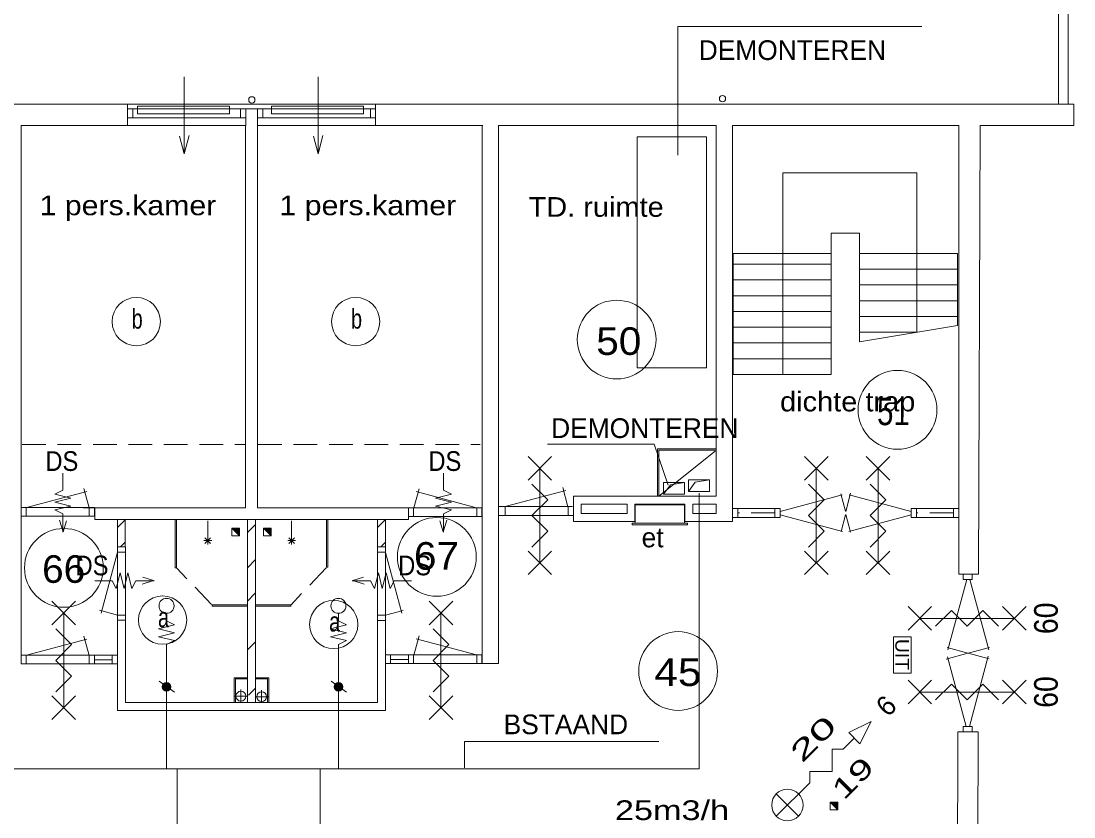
# Model space of a CAD drawing. Extents: x 295824 to 414724, y 24924 to 109024.
# Drawn here: x 320090 to 333452, y 38482 to 48585 of the extents above; entities that cross this region are included whole.
import ezdxf
from ezdxf.enums import TextEntityAlignment as Align

# ---------------------------------------------------------------- set-up
doc = ezdxf.new("R2010")
doc.units = 0
doc.header["$LTSCALE"] = 100
doc.linetypes.add('DOT_DASHED', pattern=[7.7, 5, -1.2, 0.3, -1.2])
doc.linetypes.add('MEDIUM_DASHED', pattern=[4.5, 3, -1.5])
for name, color, linetype, lineweight in [('1', 7, 'Continuous', 13), ('16', 7, 'Continuous', 13), ('24', 7, 'Continuous', 13), ('61', 7, 'Continuous', 13)]:
    doc.layers.add(name, color=color, linetype=linetype, lineweight=lineweight)

msp = doc.modelspace()

# ---------------------------------------------------------------- hatches: boundary and pattern name
at = {"layer": '24'}
for points in [[(321990.4, 40135, 1), (321881.8, 40135, 1)], [(324172.4, 40135, 1), (324063.7, 40135, 1)]]:
    msp.add_hatch(color=256, dxfattribs=at).paths.add_polyline_path(points)
at = {"layer": '61'}
for points in [[(322863, 42048.6), (322763, 42148.6), (322863, 42148.6)], [(323266, 42048.6), (323166, 42148.6), (323266, 42148.6)], [(330456.2, 38570.7), (330356.2, 38670.7), (330456.2, 38670.7)]]:
    msp.add_hatch(color=256, dxfattribs=at).paths.add_polyline_path(points)

# ---------------------------------------------------------------- linework, layer by layer
at = {"layer": '1'}
for p, q in [((321936.1, 40103.6), (321936.1, 39093.2)), ((324118, 40097), (324118, 39093.2)), ((322069.3, 38210.2), (322069.3, 39093.2)), ((323884.9, 38205.2), (323884.9, 39093.2))]:
    msp.add_line(p, q, dxfattribs=at)
msp.add_lwpolyline([(328302.1, 42694.8), (328124.9, 43212.8), (326770.6, 43212.8)], dxfattribs=at)
at = {"layer": '16'}
for p, q in [((320520.3, 42478.5), (320720.3, 42528.5)), ((325550.6, 42478.5), (325350.6, 42528.5)), ((321396.7, 41380.3), (321346.7, 41580.3)), ((324674.2, 41380.3), (324724.2, 41580.3))]:
    msp.add_line(p, q, dxfattribs=at)
at = {"layer": '24'}
for p, q in [((322161, 46901.4), (322101.4, 47123.8)), ((323859.9, 46901.4), (323800.3, 47123.8)), ((328693.9, 42590.3), (328693.9, 39093.2)), ((320623.7, 42103.1), (320578.6, 42247.3)), ((320666.1, 42238.9), (320623.7, 42103.1)), ((325404.8, 42238.9), (325447.2, 42103.1)), ((325447.2, 42103.1), (325492.2, 42247.3)), ((321772.1, 41483.7), (321627.9, 41438.7)), ((321636.3, 41526.2), (321772.1, 41483.7)), ((324434.5, 41526.2), (324298.7, 41483.7)), ((324298.7, 41483.7), (324442.9, 41438.7)), ((321936.1, 40620.3), (321936.1, 40080.9)), ((324118, 40620.3), (324118, 40112)), ((321844.5, 40205.8), (322036, 40064.1)), ((324026.4, 40205.8), (324218, 40064.1)), ((304097.2, 39093.2), (328693.9, 39093.2))]:
    msp.add_line(p, q, dxfattribs=at)
for points in [[(328423.7, 46882.6), (328423.7, 48515.9), (331521.8, 48515.9)], [(322161, 47876.3), (322161, 46901.4), (322222.6, 47131.6)], [(323859.9, 47876.3), (323859.9, 46901.4), (323921.6, 47131.6)], [(320720.3, 42528.5), (320520.3, 42578.5), (320620.3, 42628.5), (320620.3, 42847.3)], [(325350.6, 42528.5), (325550.6, 42578.5), (325450.6, 42628.5), (325450.6, 42847.3)], [(328560.2, 42611.9), (328646.7, 42731.9), (328827.5, 42761.4)], [(328243.8, 42578.6), (328330.3, 42698.6), (328511.1, 42728.1)], [(320620.3, 42097.3), (320620.3, 42328.5), (320520.3, 42378.5), (320720.3, 42428.5), (320520.3, 42478.5)], [(325450.6, 42097.3), (325450.6, 42328.5), (325550.6, 42378.5), (325350.6, 42428.5), (325550.6, 42478.5)], [(321346.7, 41580.3), (321296.7, 41380.3), (321246.7, 41480.3), (321027.9, 41480.3)], [(321777.9, 41480.3), (321546.7, 41480.3), (321496.7, 41380.3), (321446.7, 41580.3), (321396.7, 41380.3)], [(324292.9, 41480.3), (324524.2, 41480.3), (324574.2, 41380.3), (324624.2, 41580.3), (324674.2, 41380.3)], [(324724.2, 41580.3), (324774.2, 41380.3), (324824.2, 41480.3), (325042.9, 41480.3)], [(321936.1, 41070.3), (321936.1, 40970.3), (322036.1, 40920.3), (321836.1, 40870.3), (322036.1, 40820.3), (321836.1, 40770.3), (322036.1, 40720.3), (321936.1, 40670.3), (321936.1, 40620.3)], [(324118, 41070.3), (324118, 40970.3), (324218, 40920.3), (324018, 40870.3), (324218, 40820.3), (324018, 40770.3), (324218, 40720.3), (324118, 40670.3), (324118, 40620.3)], [(325717.8, 39105.3), (325717.8, 39438.6), (328182.9, 39438.6)]]:
    msp.add_lwpolyline(points, dxfattribs=at)
for points in [[(321569.6, 47405.5), (322735.6, 47405.5), (322735.6, 47505.5), (321569.6, 47505.5)], [(323268.6, 47405.5), (324434.5, 47405.5), (324434.5, 47505.5), (323268.6, 47505.5)], [(327907.4, 44182.7), (328790.1, 44182.7), (328790.1, 47115.9), (327907.4, 47115.9)], [(328560.2, 42611.9), (328827.5, 42611.9), (328827.5, 42761.4), (328560.2, 42761.4)], [(328243.8, 42578.6), (328511.1, 42578.6), (328511.1, 42728.1), (328243.8, 42728.1)]]:
    msp.add_lwpolyline(points, close=True, dxfattribs=at)
for centre, radius in [((321936.1, 41162), 95), ((324118, 41162), 95), ((321936.1, 40135), 54.3), ((324118.1, 40135), 54.3)]:
    msp.add_circle(centre, radius, dxfattribs=at)
at = {"layer": '61'}
for p, q in [((333257, 47527.9), (333257, 54115.7)), ((333377, 54115.7), (333377, 47527.2)), ((301828.9, 47527.9), (333452, 47527.9)), ((313820.3, 47527.9), (333174.1, 47527.9)), ((321441.1, 47257.3), (321441.1, 47527.3)), ((321442, 47472.1), (322941, 47472.1)), ((321442, 47358.1), (321442, 47472.1)), ((321509, 47358.1), (321509, 47471.5)), ((322874, 47472.1), (324590, 47472.1)), ((322874, 47358.5), (322874, 47472.1)), ((322941, 47359.1), (322941, 47472.1)), ((322941.1, 47257.3), (322941.1, 47472.1)), ((323090.1, 47257.3), (323090.1, 47472.1)), ((323090.9, 47358.1), (323090.9, 47472.1)), ((323157.9, 47358.1), (323157.9, 47471.5)), ((324523, 47358.5), (324523, 47471.5)), ((324590, 47359.1), (324590, 47472.1)), ((324590.1, 47257.3), (324590.1, 47527.3)), ((333452, 47527.9), (333452, 47257.9)), ((321442, 47358.1), (322940, 47358.1)), ((323090.9, 47358.1), (324589, 47358.1)), ((320090.1, 47257.9), (322941.2, 47257.9)), ((320090.1, 40532.9), (320090.1, 47257.9)), ((320090.4, 47257.9), (322940.4, 47257.9)), ((320090.5, 47257.9), (322940.5, 47257.9)), ((322940.1, 47257.9), (322940.1, 42407.9)), ((325940.1, 47257.9), (323090.1, 47257.9)), ((325949, 47257.9), (323099, 47257.9)), ((325940.1, 40428.5), (325940.1, 47257.9)), ((328910.1, 47257.9), (328910.1, 42552.9)), ((332260.1, 47257.9), (332241.7, 41563.5)), ((333452, 47257.9), (332260.1, 47257.9)), ((330368.9, 45635), (330368.9, 45892.9)), ((330368.9, 45892.9), (330732.6, 45892.9)), ((330732.6, 45635), (330732.6, 45892.9)), ((331972.5, 45635), (330732.6, 45635)), ((331972.5, 44722.2), (331972.5, 45635)), ((329129, 45498.6), (330368.9, 45498.6)), ((331972.5, 45435), (330732.6, 45435)), ((329129, 45298.6), (330368.9, 45298.6)), ((331972.5, 45235), (330732.6, 45235)), ((329129, 45098.6), (330368.9, 45098.6)), ((331972.5, 45035), (330732.6, 45035)), ((329129, 44898.6), (330368.9, 44898.6)), ((331972.5, 44835), (330732.6, 44835)), ((329129, 44698.6), (330368.9, 44698.6)), ((330732.6, 44511), (331972.5, 44722.2)), ((331460.5, 44635), (330732.6, 44635)), ((329129, 44498.6), (330368.9, 44498.6)), ((329129, 44298.6), (330368.9, 44298.6)), ((329129, 44098.6), (330368.9, 44098.6)), ((326523.6, 42757.7), (326823.6, 43057.7)), ((326823.6, 42757.7), (326523.6, 43057.7)), ((328168.4, 43154.8), (328910.1, 43154.8)), ((328168.4, 42552.9), (328168.4, 43154.8)), ((328183.4, 43139.8), (328910.1, 43139.8)), ((328183.4, 42552.9), (328183.4, 43139.8)), ((328898.2, 43126.8), (328183.9, 42555.9)), ((330031.9, 42757.7), (330331.9, 43057.7)), ((330331.9, 42757.7), (330031.9, 43057.7)), ((330816, 42757.7), (331116, 43057.7)), ((331116, 42757.7), (330816, 43057.7)), ((326673.6, 42907.7), (326673.6, 41707.7)), ((330181.9, 42907.7), (330181.9, 41707.7)), ((330966, 42907.7), (330966, 41707.7)), ((320953.4, 42407.1), (320888.4, 42649.8)), ((325075.2, 42405.1), (325140.3, 42647.8)), ((326234.9, 42421.6), (327002.2, 42627.2)), ((327029.5, 42419.5), (326964.4, 42662.2)), ((320158.9, 42409.2), (320926.2, 42614.8)), ((325869.8, 42407.2), (325102.5, 42612.8)), ((327099.3, 42232.9), (327099.3, 42552.9)), ((328910.1, 42552.9), (327099.3, 42552.9)), ((328910.1, 42552.9), (328512.1, 42552.9)), ((330512, 42572.2), (329725.6, 42361.4)), ((330553, 42361.5), (330493.5, 42583.4)), ((330556, 42361.1), (330617.3, 42590)), ((330597.9, 42572.2), (331385.2, 42361.3)), ((320156.3, 42299.1), (320156.3, 42409.1)), ((322940.1, 42407.9), (320878.9, 42407.9)), ((320956.3, 42299.1), (320956.3, 42409.1)), ((321023.3, 42299.1), (321023.3, 42409.1)), ((323088.9, 42407.9), (325031.4, 42407.9)), ((323090.4, 42407.9), (325938.2, 42407.9)), ((325005.4, 42297.1), (325005.4, 42407.1)), ((325072.4, 42297.1), (325072.4, 42407.1)), ((325872.4, 42297.1), (325872.4, 42407.1)), ((325938.3, 42297.4), (325938.3, 42407.8)), ((326152.8, 42421), (327089.5, 42421)), ((326232.3, 42311.5), (326232.3, 42421.5)), ((327032.3, 42311.5), (327032.3, 42421.5)), ((327780.3, 42452.9), (327199.3, 42452.9)), ((327780.3, 42332.9), (327780.3, 42452.9)), ((327880.3, 42234.5), (327880.3, 42452.9)), ((328515.5, 42452.9), (327880.3, 42452.9)), ((327884.6, 42217.1), (327884.6, 42444.5)), ((327884.6, 42444.5), (328508.9, 42444.5)), ((328508.9, 42209.4), (328508.9, 42444.5)), ((328515.5, 42232.9), (328515.5, 42452.9)), ((328910.1, 42452.9), (328615.5, 42452.9)), ((328910.1, 42452.9), (328910.1, 42332.9)), ((329120, 42398.2), (329724.8, 42398.2)), ((329120, 42282), (329120, 42396)), ((329187, 42282.9), (329187, 42396.9)), ((329657.8, 42282.9), (329657.8, 42396.9)), ((329724.8, 42282), (329724.8, 42398.2)), ((331384.8, 42282), (331384.8, 42398.2)), ((331384.8, 42398.2), (331990, 42398.2)), ((331451.8, 42282.9), (331451.8, 42396.9)), ((331923, 42281.8), (331923, 42394.9)), ((331990, 42280.9), (331990, 42394.9)), ((321021.2, 42299.4), (320090.4, 42299.4)), ((321024.2, 42257.9), (324614.3, 42257.9)), ((321314, 41911.5), (321314, 42257.9)), ((321314, 42157.2), (321414.4, 42257.6)), ((321412.7, 41911.5), (321412.7, 42257.9)), ((322046.7, 41644.6), (322046.7, 42253)), ((322064.7, 41644.6), (322064.7, 42253)), ((322459.5, 42039.2), (322459.5, 42239.2)), ((322963.9, 42257.9), (322963.9, 39932.9)), ((323063.9, 42257.9), (323063.9, 39932.9)), ((323524, 42039.2), (323524, 42239.2)), ((323964.5, 41650.7), (323964.5, 42255.5)), ((323982.5, 41650.7), (323982.5, 42255.5)), ((324614.3, 41911.9), (324614.3, 42258.3)), ((324614.5, 42157.2), (324714.9, 42257.6)), ((324714.1, 41911.5), (324714.1, 42257.9)), ((325007.5, 42297.4), (325938.3, 42297.4)), ((326152.8, 42307.3), (327093.8, 42307.3)), ((327880.3, 42232.9), (327099.3, 42232.9)), ((329120.1, 42232.9), (328515.5, 42232.9)), ((329120.6, 42282), (329724.8, 42282)), ((329724.9, 42319), (330514.2, 42107.5)), ((330497.1, 42106.1), (330554, 42318.6)), ((330615.2, 42097.9), (330555.9, 42319.3)), ((331385, 42319.1), (330593.9, 42107.1)), ((331384.8, 42282), (331989.4, 42282)), ((322964.4, 42093), (323062.9, 42191.5)), ((327845.3, 42209.4), (328546.5, 42209.4)), ((327845.3, 42191.9), (327845.3, 42209.4)), ((327845.3, 42191.9), (328546.5, 42191.9)), ((328546.5, 42191.9), (328546.5, 42209.4)), ((321356.4, 41913.2), (321413, 41969.9)), ((322509.5, 41989.2), (322409.5, 41989.2)), ((322494.9, 42024.5), (322424.2, 41953.8)), ((322494.9, 41953.8), (322424.2, 42024.5)), ((322459.5, 42039.2), (322459.5, 41939.2)), ((323574, 41989.2), (323474, 41989.2)), ((323559.4, 42024.5), (323488.7, 41953.8)), ((323559.4, 41953.8), (323488.7, 42024.5)), ((323524, 42039.2), (323524, 41939.2)), ((324658.3, 41913.2), (324714.9, 41969.9)), ((321314, 41841.3), (321107.1, 41069.1)), ((321313.8, 40977.9), (321313.8, 41911.9)), ((321413.8, 41911.9), (321313.8, 41911.9)), ((321413.9, 41844.9), (321313.8, 41844.9)), ((321413.8, 41911.9), (321413.8, 40977.9)), ((324613.7, 41844.5), (324713.9, 41844.5)), ((324613.9, 41911.5), (324613.9, 40977.5)), ((324614.3, 41911.5), (324714.5, 41911.5)), ((324713.6, 41841), (324920.5, 41068.7)), ((324713.9, 40976.7), (324713.9, 41911.5)), ((326523.6, 41557.7), (326823.6, 41857.7)), ((326823.6, 41557.7), (326523.6, 41857.7)), ((330031.9, 41557.7), (330331.9, 41857.7)), ((330331.9, 41557.7), (330031.9, 41857.7)), ((330816, 41557.7), (331116, 41857.7)), ((331116, 41557.7), (330816, 41857.7)), ((322964.4, 41645.4), (323062.9, 41743.9)), ((322046.7, 41644.6), (322064.7, 41644.6)), ((323964.5, 41650.7), (323982.5, 41650.7)), ((324714, 41578.4), (324714, 41468)), ((332241.7, 41563.5), (331990.1, 41563.5)), ((331851.1, 40602.2), (332090.7, 41496.3)), ((332130.7, 41496.3), (332369.8, 40603.9)), ((322964.4, 41222.9), (323062.9, 41321.4)), ((320480.8, 40919.8), (320780.8, 41219.8)), ((320780.8, 40919.8), (320480.8, 41219.8)), ((322963.5, 41158.7), (322513.2, 41158.7)), ((323514.9, 41176.7), (323064.9, 41176.7)), ((323514.9, 41158.7), (323064.9, 41158.7)), ((323514.9, 41176.7), (323514.9, 41158.7)), ((325268.5, 40919.8), (325568.5, 41219.8)), ((325568.5, 40919.8), (325268.5, 41219.8)), ((320630.8, 41069.8), (320630.8, 39869.8)), ((321314, 41043.9), (321086.7, 41104.8)), ((321413.6, 41044.9), (321314.3, 41044.9)), ((324614, 41044.5), (324713.4, 41044.5)), ((324713.6, 41043.5), (324940.9, 41104.4)), ((325418.5, 41069.8), (325418.5, 39869.8)), ((331646.2, 40852.6), (331346.2, 41152.6)), ((331646.2, 41152.6), (331346.2, 40852.6)), ((332846.2, 40852.6), (332546.2, 41152.6)), ((332846.2, 41152.6), (332546.2, 40852.6)), ((321413.8, 40977.9), (321313.8, 40977.9)), ((321313.9, 40975.3), (321313.9, 40188.2)), ((321413.9, 40638.2), (321413.9, 40975.3)), ((324613.9, 40977.5), (324613.9, 39932.9)), ((324613.9, 40977.5), (324713.9, 40977.5)), ((324713.9, 40977.5), (324713.9, 40532.9)), ((331496.2, 41002.6), (332696.2, 41002.6)), ((320952.2, 40532.9), (320887.2, 40775.7)), ((325075.2, 40536.8), (325140.3, 40779.5)), ((320157.7, 40535.1), (320924.9, 40740.7)), ((322964.4, 40603), (323062.9, 40701.4)), ((325869.8, 40539), (325102.5, 40744.6)), ((332106.9, 40561.2), (331843.4, 40631.8)), ((332382.4, 40635.1), (332108.4, 40561.7)), ((320155.1, 40424.9), (320155.1, 40534.9)), ((320955.1, 40424.9), (320955.1, 40534.9)), ((321022.1, 40424.9), (321022.1, 40534.9)), ((321247.6, 40424.9), (321247.6, 40534.9)), ((324779.9, 40428.8), (324779.9, 40538.8)), ((325005.4, 40428.8), (325005.4, 40538.8)), ((325072.4, 40428.8), (325072.4, 40538.8)), ((325872.4, 40428.8), (325872.4, 40538.8)), ((332107.3, 40560.2), (331828.5, 40485.5)), ((331847.3, 40516.5), (332084.6, 39630.7)), ((332376.5, 40488.2), (332109.1, 40559.9)), ((332124.6, 39630.6), (332363.2, 40520.9)), ((321022.9, 40475.7), (321247.6, 40475.7)), ((325004.6, 40479.6), (324779.9, 40479.6)), ((325959.8, 40428.6), (326073.8, 40428.6)), ((322796.2, 40248), (322963.9, 40248)), ((322796.2, 40248), (322796.2, 39932.9)), ((322810.5, 40234.4), (322963.9, 40234.4)), ((322810.5, 40234.4), (322810.5, 39934)), ((323064, 40234.4), (323218.7, 40234.4)), ((323065, 40248), (323233.7, 40248)), ((323218.7, 39932.9), (323218.7, 40234.4)), ((323233.7, 39932.9), (323233.7, 40248)), ((322977.5, 40026.8), (323062.9, 40112.1)), ((331646.2, 39917.2), (331346.2, 40217.2)), ((331646.2, 40217.2), (331346.2, 39917.2)), ((332846.2, 39917.2), (332546.2, 40217.2)), ((332846.2, 40217.2), (332546.2, 39917.2)), ((320480.8, 39719.8), (320780.8, 40019.8)), ((320780.8, 39719.8), (320480.8, 40019.8)), ((325268.5, 39719.8), (325568.5, 40019.8)), ((325568.5, 39719.8), (325268.5, 40019.8)), ((331496.2, 40067.2), (332696.2, 40067.2)), ((332235.2, 39563.5), (332210.1, 31845.6)), ((329674.7, 38774.8), (329957.6, 38492))]:
    msp.add_line(p, q, dxfattribs=at)
at = {"layer": '61', "linetype": 'MEDIUM_DASHED'}
for p, q in [((320103.3, 43208.1), (322935.1, 43208.1)), ((323098.4, 43208.1), (325916.3, 43208.1)), ((329656.2, 42342.2), (329186.7, 42342.2)), ((331921.7, 42342.2), (331452.9, 42342.2)), ((322505.8, 41179.8), (322064, 41644.8)), ((323960.1, 41643.1), (323516.1, 41175.8))]:
    msp.add_line(p, q, dxfattribs=at)
at = {"layer": '61', "linetype": 'DOT_DASHED'}
for p, q in [((322879.5, 39934.8), (322879.5, 40098.9)), ((323142.7, 39933.5), (323142.7, 40092.8)), ((322968, 40015.2), (322804, 40015.2)), ((323227.8, 40007.7), (323063.7, 40007.7))]:
    msp.add_line(p, q, dxfattribs=at)
at = {"layer": '61'}
for points in [[(325940.4, 47257.9), (323090.4, 47257.9), (323090.4, 42407.9)], [(325940.5, 47257.9), (323090.5, 47257.9), (323090.5, 42407.9)], [(326150.1, 42234.5), (326150.1, 47257.9), (328910.1, 47257.9)], [(329120.1, 42232.9), (329120.1, 47257.9), (331990.1, 47257.9), (331990.1, 41563.5)], [(329757.2, 44098.6), (329757.2, 46659.3), (331460, 46659.3), (331460, 44634.9)], [(331972.5, 45635), (330732.6, 45635), (330732.6, 44511)], [(326573.6, 42707.7), (326773.6, 42507.7), (326573.6, 42307.7), (326773.6, 42107.7), (326573.6, 41907.7)], [(330081.9, 42707.7), (330281.9, 42507.7), (330081.9, 42307.7), (330281.9, 42107.7), (330081.9, 41907.7)], [(330866, 42707.7), (331066, 42507.7), (330866, 42307.7), (331066, 42107.7), (330866, 41907.7)], [(320090.4, 42299.4), (320090.4, 42409.8), (321023.7, 42409.8)], [(322938.9, 42407.9), (321024.2, 42407.9), (321024.2, 42257.9)], [(325005, 42407.8), (325005, 42257.9), (324599.6, 42257.9)], [(327780.3, 42332.9), (327199.3, 42332.9), (327199.3, 42452.9)], [(328910.1, 42332.9), (328615.5, 42332.9), (328615.5, 42452.9)], [(326150.1, 42232.9), (326150.1, 40428.5), (325940.1, 40428.5)], [(322763, 42148.6), (322863, 42148.6), (322863, 42048.6)], [(323166, 42148.6), (323266, 42148.6), (323266, 42048.6)], [(321413.9, 41158.7), (321413.9, 39932.9), (323293.9, 39932.9)], [(322963.5, 41176.7), (322513.2, 41176.7), (322513.2, 41158.7)], [(331696.2, 40902.6), (331896.2, 41102.6), (332096.2, 40902.6), (332296.2, 41102.6), (332496.2, 40902.6)], [(320530.8, 40869.8), (320730.8, 40669.8), (320530.8, 40469.8), (320730.8, 40269.8), (320530.8, 40069.8)], [(323088.7, 39932.9), (324613.9, 39932.9), (324613.9, 40882.9)], [(325318.5, 40869.8), (325518.5, 40669.8), (325318.5, 40469.8), (325518.5, 40269.8), (325318.5, 40069.8)], [(321313.9, 40432.9), (321313.9, 39832.9), (324713.9, 39832.9), (324713.9, 40432.9)], [(331696.2, 39967.2), (331896.2, 40167.2), (332096.2, 39967.2), (332296.2, 40167.2), (332496.2, 39967.2)], [(331973.9, 37762.8), (331980.4, 39563.5), (332235.2, 39563.5)], [(329674.7, 38492), (330099, 38916.3), (330099, 39057.7), (330381.8, 39057.7), (330381.8, 39340.5), (330523.3, 39340.5), (330664.7, 39482)], [(330356.2, 38670.7), (330456.2, 38670.7), (330456.2, 38570.7)]]:
    msp.add_lwpolyline(points, dxfattribs=at)
for points in [[(330368.9, 45635), (329129, 45635), (329129, 44098.6), (330368.9, 44098.6)], [(322763, 42148.6), (322763, 42048.6), (322863, 42048.6)], [(322863, 42048.6), (322763, 42148.6), (322863, 42148.6)], [(323166, 42148.6), (323166, 42048.6), (323266, 42048.6)], [(323266, 42048.6), (323166, 42148.6), (323266, 42148.6)], [(332046.2, 41496.3), (332046.2, 41563.3), (332162.4, 41563.3), (332162.4, 41496.3)], [(331163.5, 40768.9), (331163.5, 40309.3), (331388.1, 40309.3), (331388.1, 40768.9)], [(320089.2, 40425.3), (320089.2, 40535.6), (321313.5, 40535.6), (321313.5, 40425.3)], [(325938.3, 40429.1), (325938.3, 40539.5), (324714, 40539.5), (324714, 40429.1)], [(330735.4, 39411.2), (330594, 39552.7), (330876.8, 39694.1)], [(332046.2, 39563.6), (332046.2, 39630.6), (332162.4, 39630.6), (332162.4, 39563.6)], [(330356.2, 38670.7), (330356.2, 38570.7), (330456.2, 38570.7)], [(330456.2, 38570.7), (330356.2, 38670.7), (330456.2, 38670.7)]]:
    msp.add_lwpolyline(points, close=True, dxfattribs=at)
for centre, radius in [((323018.5, 47584.2), 40), ((328991.8, 47600.4), 40), ((321552.2, 44769.7), 306.3), ((324336.3, 44769.7), 306.3), ((327649.2, 44541.3), 500), ((331212.8, 43649.8), 500), ((325366.2, 41783), 500), ((320633.2, 41643.7), 500), ((321886.3, 40980.6), 306.3), ((324057.9, 40924.8), 306.3), ((328428.7, 40334.2), 500), ((322879.5, 40015.2), 62.5), ((323143.3, 40008.4), 62.5), ((329816.1, 38633.4), 200)]:
    msp.add_circle(centre, radius, dxfattribs=at)

# ---------------------------------------------------------------- texts
at = {"layer": '24'}
for s, p in [('DEMONTEREN', (328690.2, 48090.9)), ('DEMONTEREN', (326817.3, 43292.3)), ('BSTAAND', (326214.6, 39532.2))]:
    msp.add_text(s, height=250, dxfattribs=at).set_placement(p)
for s, width, p in [('DS', 0.9, (320398.4, 42874.3)), ('DS', 0.9, (325259, 42874.3)), ('DS', 0.9, (320781.5, 41549.3)), ('DS', 0.9, (324875.9, 41549.3)), ('25m3/h', 1.3, (327626.5, 38442.7))]:
    msp.add_text(s, height=250, dxfattribs=dict(at, width=width)).set_placement(p)
at = {"layer": '61'}
for s, height, width, p in [('1 pers.kamer', 250, 1.15, (320324.6, 46120.2)), ('1 pers.kamer', 250, 1.15, (323369, 46120.2)), ('TD. ruimte', 250, 1.1, (326530.2, 46100.3)), ('b', 250, 0.75, (321494.2, 44680.6)), ('b', 250, 0.75, (324278.3, 44680.6)), ('50', 350, 1.1, (327389.2, 44346.9)), ('dichte trap', 250, 1.1, (329721.9, 43630.2)), ('51', 350, 0.8, (330952.9, 43455.3)), ('a', 250, 0.75, (321828.3, 40891.4)), ('a', 250, 0.75, (323999.9, 40835.7))]:
    msp.add_text(s, height=height, dxfattribs=dict(at, width=width)).set_placement(p)
msp.add_text('et', height=250, dxfattribs=at).set_placement((327965.5, 41904.5))
for s, width, p in [('67', 1.1, (325361.9, 41621)), ('66', 1.05, (320630.3, 41453.9)), ('45', 1.15, (328425.8, 40144.4))]:
    msp.add_text(s, height=350, dxfattribs=dict(at, width=width)).set_placement(p, align=Align.CENTER)
at = {"layer": '61', "width": 0.9}
for p in [(333246.2, 41003.4), (333246.2, 40068)]:
    msp.add_text('60', height=300, rotation=90, dxfattribs=at).set_placement(p, align=Align.CENTER)
at = {"layer": '61'}
for s, height, rotation, width, p in [('UIT', 175, 270, 1.05, (331184.9, 40742.2)), ('20', 250, 45, 1.75, (330001.4, 39156)), ('19', 250, 45, 1.55, (330529.8, 38683.7))]:
    msp.add_text(s, height=height, rotation=rotation, dxfattribs=dict(at, width=width)).set_placement(p)
msp.add_text('6', height=250, rotation=45, dxfattribs=at).set_placement((331091.3, 39739.9))

doc.saveas('drawing.dxf')
